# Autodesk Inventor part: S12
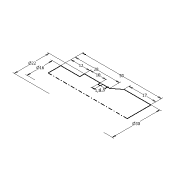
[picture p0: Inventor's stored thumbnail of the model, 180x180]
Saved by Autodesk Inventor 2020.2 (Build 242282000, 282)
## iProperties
Created: 2015-05
Part Number: S12
Material: Ogólny
Document SubType Name: Modeling
Designer: F.Stasiak
Density: 1 g/cm^3
Appearance: Domyślna
Manager: www.cadconsulting.pl
Company: Fabian Stasiak CAD Consulting
Author: F.Stasiak
Subject: Zbiór ćwiczeń. Autodesk Inventor 2020. Kurs podstawowy
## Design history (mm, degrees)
sketch "Szkic1"
  geometry: L1 (-50, 0)-(-50, 8); L2 (-50, 8)-(-38, 8); L3 (-38, 8)-(-38, 11); L4 (-38, 11)-(-28, 11); L5 (-28, 11)-(-28, 9.5); L6 (-28, 9.5)-(-26.5, 9.5); L7 (-26.5, 9.5)-(-26.5, 11); L8 (-26.5, 11)-(-22, 11); L9 (-22, 11)-(-17, 15); L10 (-17, 15)-(0, 15); L11 (-50, 0)-(0, 0); L12 (0, 0)-(0, 15)
  constraints: 24 end point, 7 perpendicular, 2 horizontal, 2 point on line
  dimensions: "d2" = 12 distance of L1.end L2.end; "d4" = 10 distance of L3.end L4.end; "d5" = 1.5 distance of L4.end L5.end; "d6" = 1.5 distance of L5.end L6.end; "d8" = 16 diameter of L2 L11; "d9" = 22 diameter of L4 L11; "d10" = 30 diameter of L10 L11; "d11" = 28 distance from line of L8.end L1; "d12" = 17 distance of L9.end L10.end; "d13" = 50 distance of L1.start L11.end
